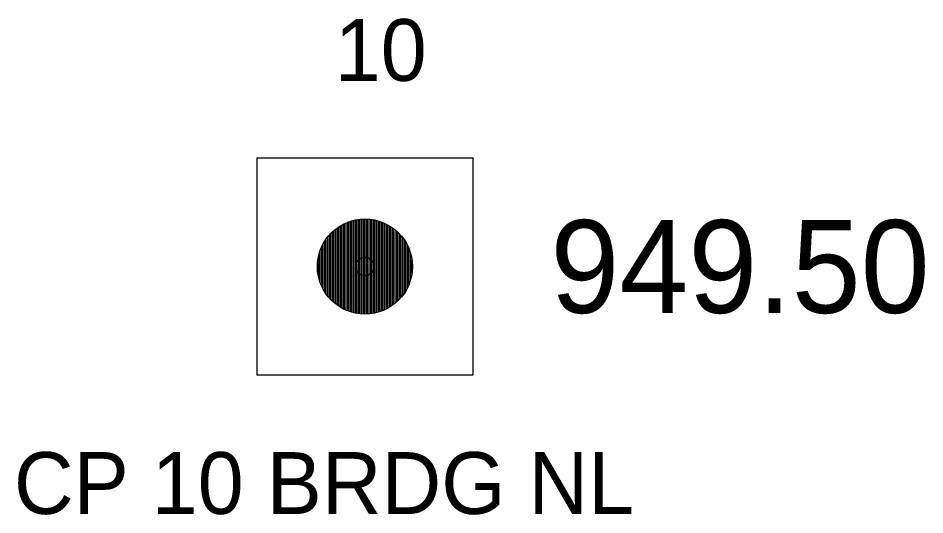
# Model space of a CAD drawing. Extents: x 1393163 to 1398407, y 1072670 to 1074651.
# Drawn here: x 1394449.44 to 1394464.11, y 1073434.75 to 1073442.78 of the extents above; entities that cross this region are included whole.
import ezdxf

# ---------------------------------------------------------------- set-up
doc = ezdxf.new("R2010")
doc.units = 0
for name, color, linetype in [('RD_HC_Survey', 7, 'Continuous'), ('RD_HC_Survey_ELEV', 7, 'Continuous'), ('RD_HC_Survey_txCode', 7, 'Continuous'), ('RD_SMD_Locator', 7, 'Continuous')]:
    doc.layers.add(name, color=color, linetype=linetype)

msp = doc.modelspace()

# ---------------------------------------------------------------- linework, layer by layer
at = {"layer": 'RD_HC_Survey'}
for p, q in [((1394454.721, 1073438.072), (1394454.721, 1073439.464)), ((1394454.746, 1073438.061), (1394454.746, 1073439.475)), ((1394454.771, 1073438.05), (1394454.771, 1073439.485)), ((1394454.796, 1073438.041), (1394454.796, 1073439.494)), ((1394454.82, 1073438.033), (1394454.82, 1073439.503)), ((1394454.845, 1073438.026), (1394454.845, 1073439.51)), ((1394454.87, 1073438.02), (1394454.87, 1073439.516)), ((1394454.895, 1073438.014), (1394454.895, 1073439.522)), ((1394454.919, 1073438.009), (1394454.919, 1073439.526)), ((1394454.944, 1073438.006), (1394454.944, 1073439.53)), ((1394454.969, 1073438.003), (1394454.969, 1073439.533)), ((1394454.994, 1073438), (1394454.994, 1073439.535)), ((1394455.018, 1073437.999), (1394455.018, 1073439.537)), ((1394455.043, 1073437.998), (1394455.043, 1073439.537)), ((1394455.068, 1073437.999), (1394455.068, 1073439.537)), ((1394455.093, 1073438), (1394455.093, 1073439.536)), ((1394455.117, 1073438.001), (1394455.117, 1073439.534)), ((1394455.142, 1073438.004), (1394455.142, 1073439.532)), ((1394455.167, 1073438.007), (1394455.167, 1073439.528)), ((1394455.192, 1073438.012), (1394455.192, 1073439.524)), ((1394455.216, 1073438.017), (1394455.216, 1073439.519)), ((1394455.241, 1073438.023), (1394455.241, 1073439.513)), ((1394455.266, 1073438.03), (1394455.266, 1073439.506)), ((1394455.291, 1073438.037), (1394455.291, 1073439.498)), ((1394455.315, 1073438.046), (1394455.315, 1073439.49)), ((1394455.34, 1073438.056), (1394455.34, 1073439.48)), ((1394455.365, 1073438.066), (1394455.365, 1073439.47)), ((1394455.39, 1073438.078), (1394455.39, 1073439.458)), ((1394454.523, 1073438.206), (1394454.523, 1073439.33)), ((1394454.548, 1073438.184), (1394454.548, 1073439.352)), ((1394454.573, 1073438.163), (1394454.573, 1073439.372)), ((1394454.598, 1073438.145), (1394454.598, 1073439.391)), ((1394454.622, 1073438.128), (1394454.622, 1073439.408)), ((1394454.647, 1073438.112), (1394454.647, 1073439.424)), ((1394454.672, 1073438.097), (1394454.672, 1073439.439)), ((1394454.697, 1073438.084), (1394454.697, 1073439.452)), ((1394455.414, 1073438.091), (1394455.414, 1073439.445)), ((1394455.439, 1073438.105), (1394455.439, 1073439.431)), ((1394455.464, 1073438.12), (1394455.464, 1073439.416)), ((1394455.489, 1073438.136), (1394455.489, 1073439.399)), ((1394455.513, 1073438.154), (1394455.513, 1073439.381)), ((1394455.538, 1073438.174), (1394455.538, 1073439.362)), ((1394455.563, 1073438.195), (1394455.563, 1073439.341)), ((1394455.588, 1073438.218), (1394455.588, 1073439.317)), ((1394454.4, 1073438.355), (1394454.4, 1073439.181)), ((1394454.424, 1073438.318), (1394454.424, 1073439.217)), ((1394454.449, 1073438.286), (1394454.449, 1073439.25)), ((1394454.474, 1073438.257), (1394454.474, 1073439.279)), ((1394454.499, 1073438.23), (1394454.499, 1073439.306)), ((1394455.612, 1073438.244), (1394455.612, 1073439.292)), ((1394455.637, 1073438.272), (1394455.637, 1073439.264)), ((1394455.662, 1073438.303), (1394455.662, 1073439.233)), ((1394455.687, 1073438.337), (1394455.687, 1073439.199)), ((1394454.326, 1073438.506), (1394454.326, 1073439.03)), ((1394454.35, 1073438.446), (1394454.35, 1073439.09)), ((1394454.375, 1073438.397), (1394454.375, 1073439.139)), ((1394455.711, 1073438.376), (1394455.711, 1073439.16)), ((1394455.736, 1073438.421), (1394455.736, 1073439.114)), ((1394455.761, 1073438.476), (1394455.761, 1073439.06)), ((1394454.301, 1073438.589), (1394454.301, 1073438.947)), ((1394455.786, 1073438.545), (1394455.786, 1073438.991)), ((1394455.81, 1073438.656), (1394455.81, 1073438.88))]:
    msp.add_line(p, q, dxfattribs=at)
msp.add_lwpolyline([(1394456.799, 1073440.518), (1394453.299, 1073440.518), (1394453.299, 1073437.018), (1394456.799, 1073437.018)], close=True, dxfattribs=at)
msp.add_circle((1394455.049, 1073438.768), 0.769, dxfattribs=at)
at = {"layer": 'RD_SMD_Locator'}
msp.add_circle((1394455.049, 1073438.768), 0.15, dxfattribs=at)

# ---------------------------------------------------------------- texts
at = {"layer": 'RD_HC_Survey_ELEV'}
msp.add_text('949.50', height=1.5, dxfattribs=at).set_placement((1394458.049, 1073438.018))
at = {"layer": 'RD_HC_Survey_txCode'}
for s, p in [('10', (1394454.561, 1073441.768)), ('CP 10 BRDG NL', (1394449.372, 1073434.768))]:
    msp.add_text(s, height=1, dxfattribs=at).set_placement(p)

doc.saveas('drawing.dxf')
